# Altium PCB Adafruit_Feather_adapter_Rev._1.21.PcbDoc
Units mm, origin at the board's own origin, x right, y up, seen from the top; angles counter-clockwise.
Board outline 65 x 56 mm, 2 copper layers (Top Layer, Bottom Layer), stack 1.586 mm thick; 51 components, 43 nets, 191 pads, 149 vias.
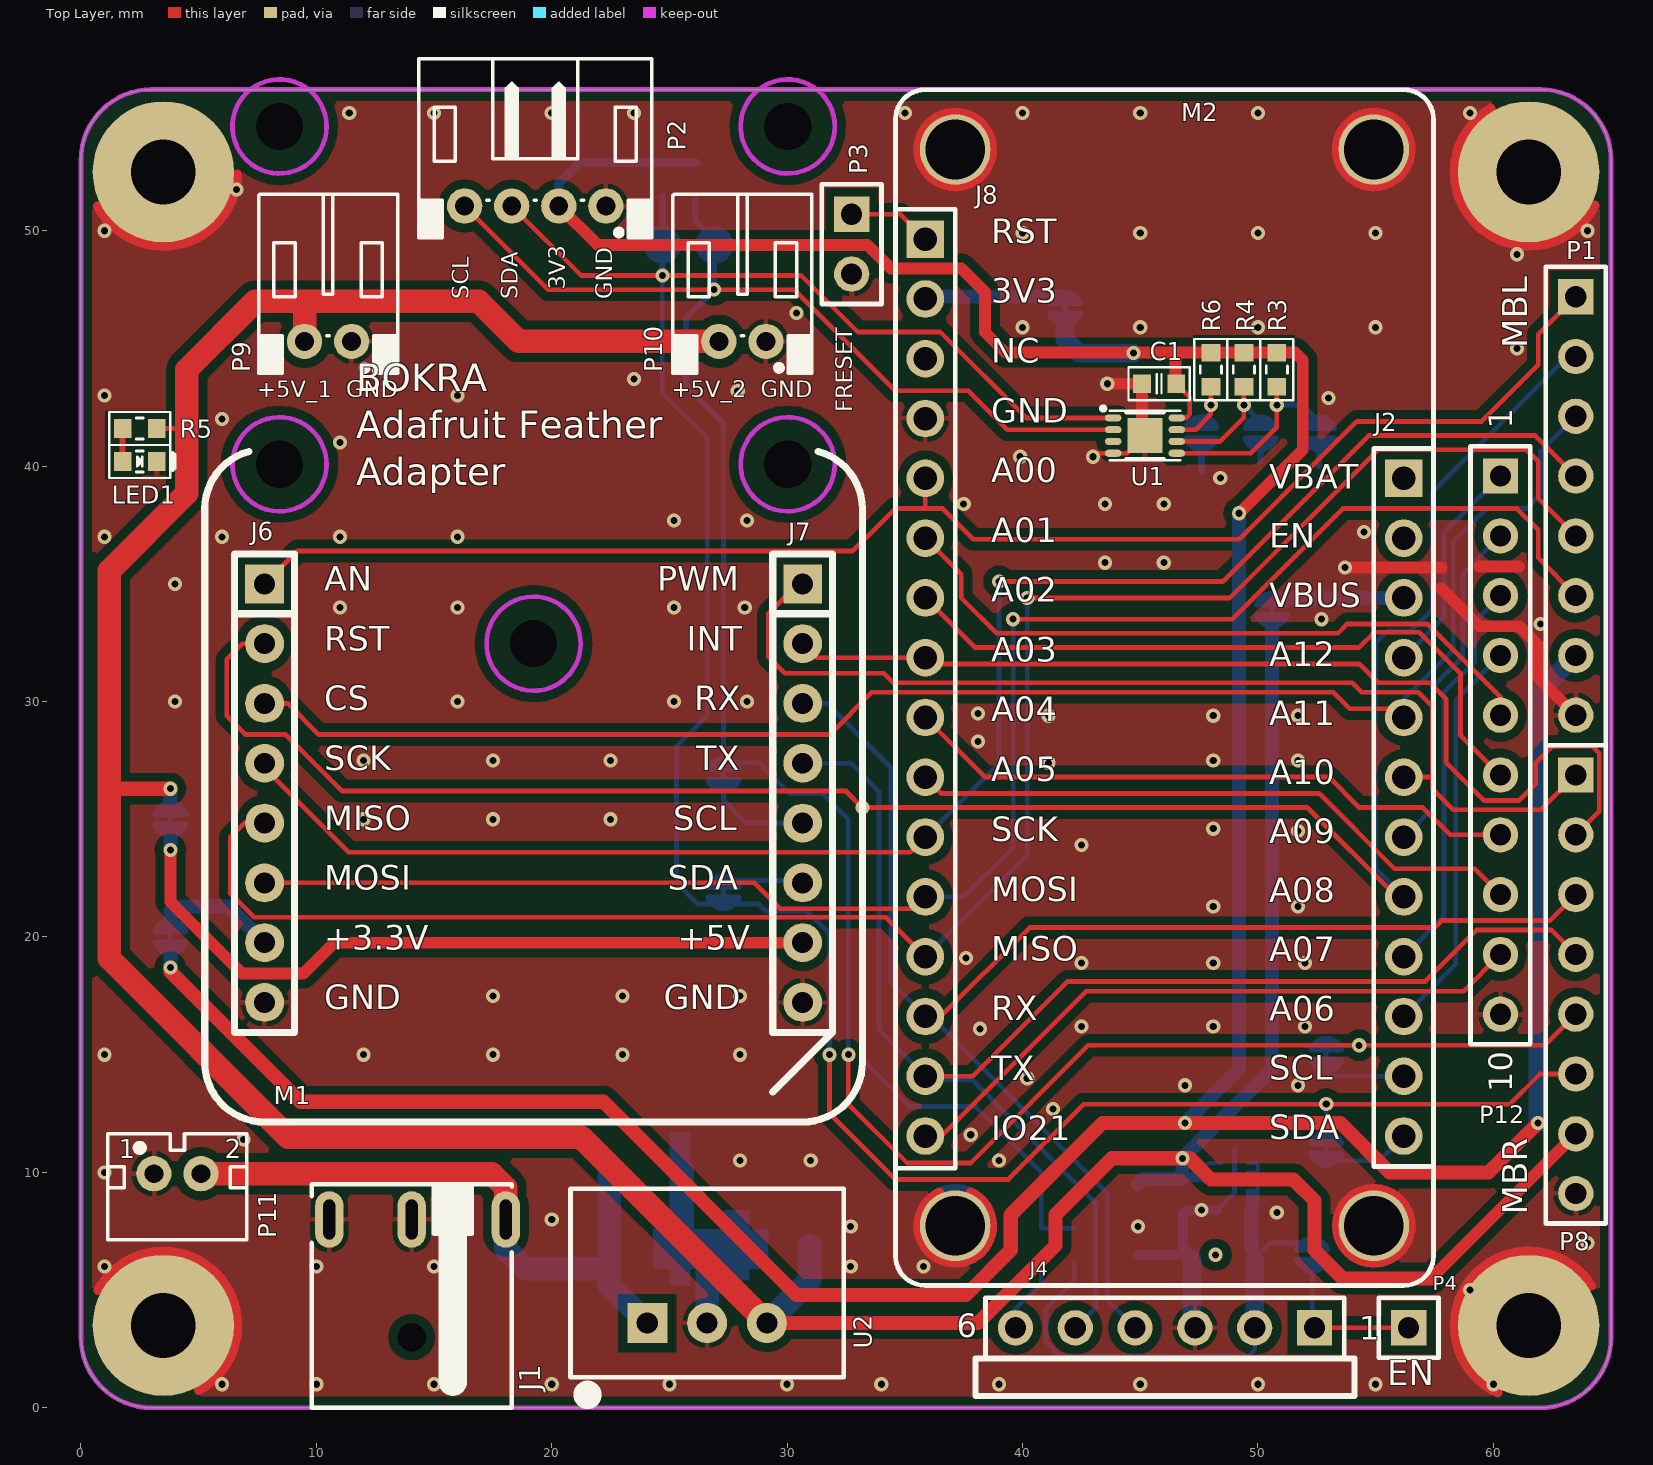
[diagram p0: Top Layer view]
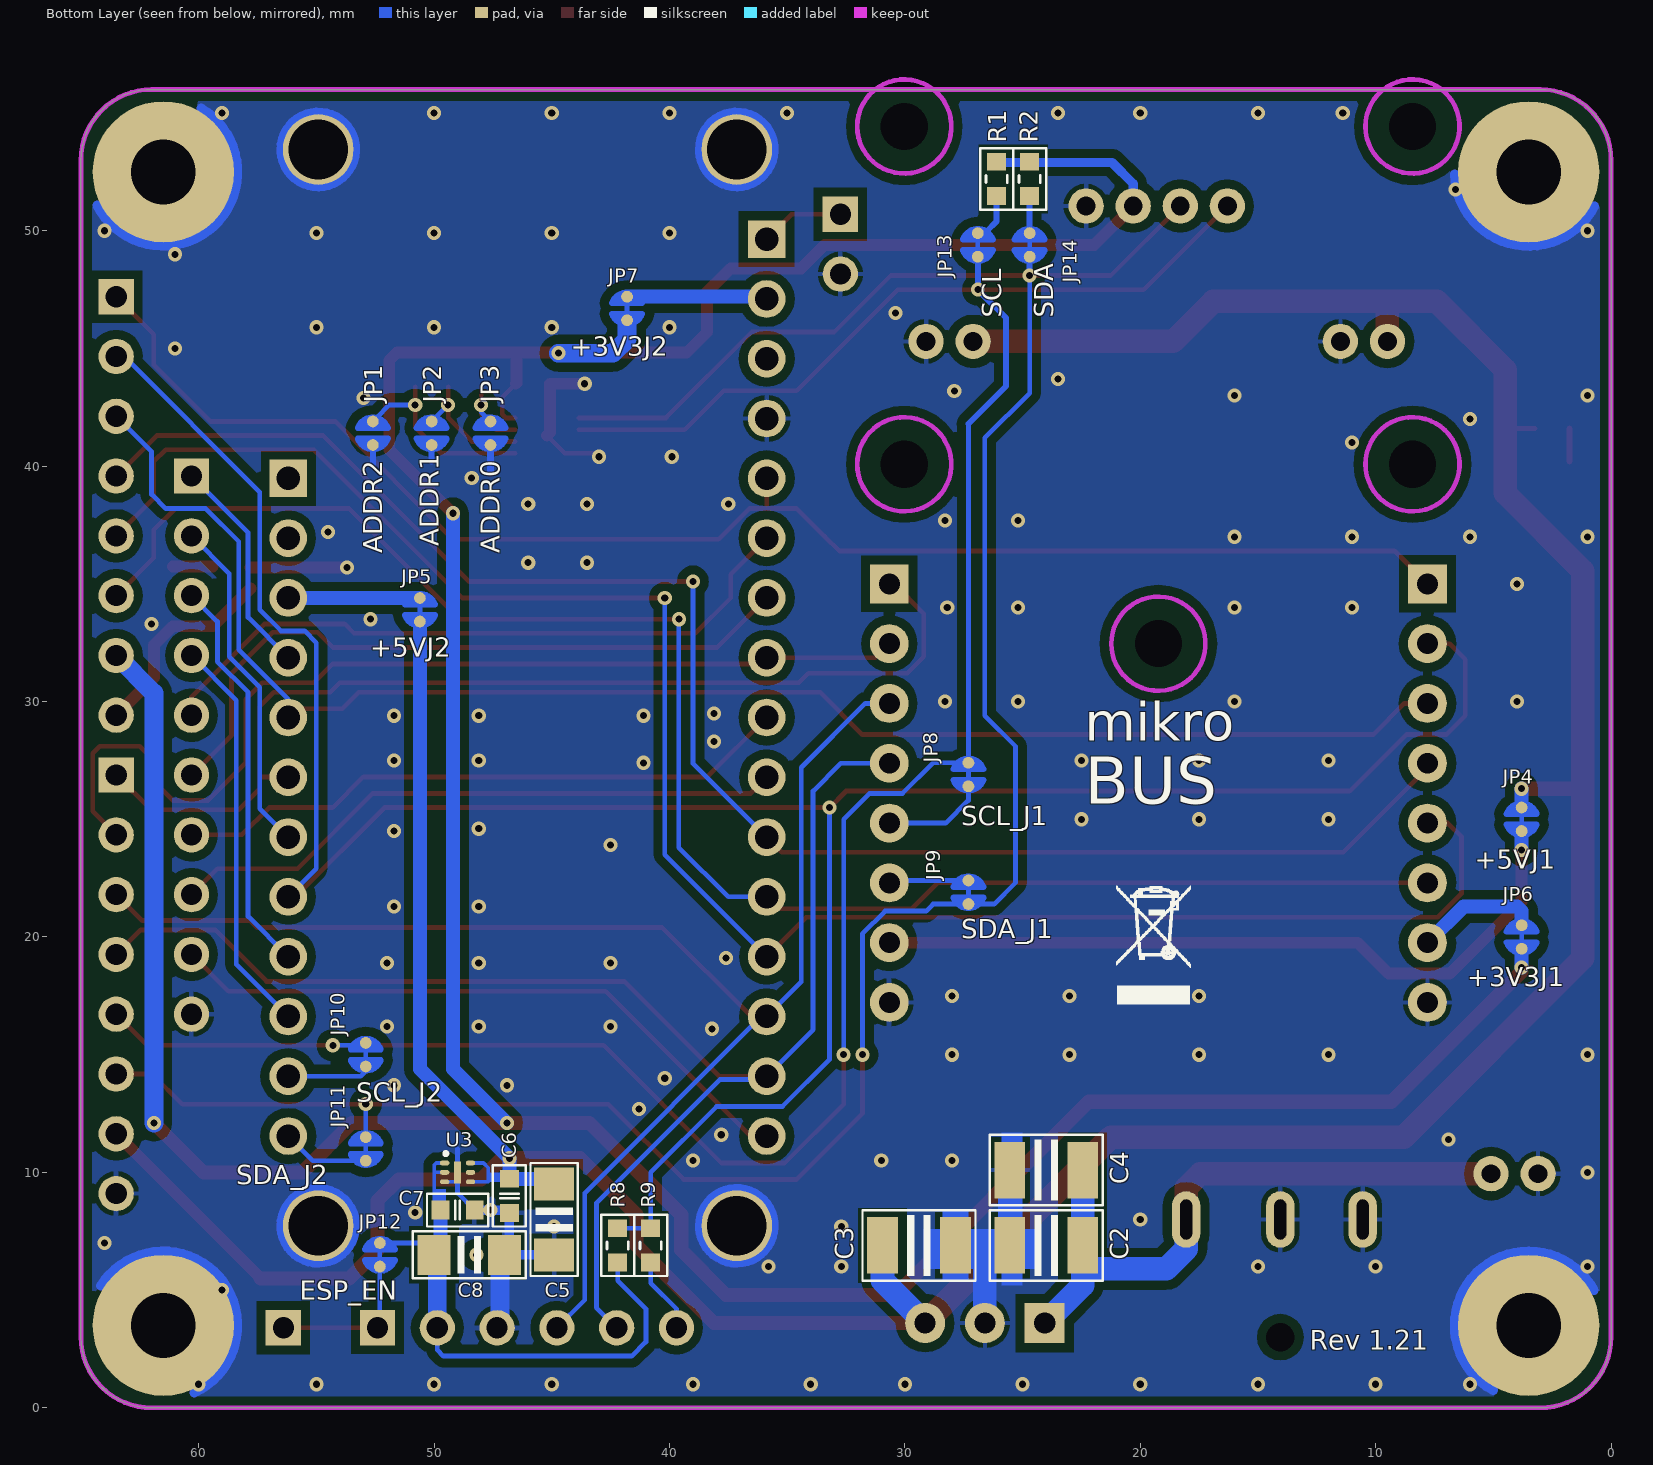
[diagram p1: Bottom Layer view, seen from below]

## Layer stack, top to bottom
Top Solder: solder mask 0.0102, Solder Resist, Dk 3.5
Top Layer: signal copper 0.018
Dielectric1: core 1.55, FR-4, Dk 4.8
Bottom Layer: signal copper 0.018
Bottom Solder: solder mask 0.0102, Solder Resist, Dk 3.5

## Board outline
0,3 0,53 cw(c3,53) 3,56 62,56 cw(c62,53) 65,53 65,3 cw(c62,3) 62,0 3,0 cw(c3,3)

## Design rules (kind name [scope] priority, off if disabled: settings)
BoardOutlineClearance [All] p1: gap=0.25 except(0: Arc-SplitContinuation Track-SplitContinuation SMDPad-SplitContinuation THPad-SplitContinuation Via-SplitContinuation Fill-SplitContinuation Poly-SplitContinuation Region-SplitContinuation Text-SplitContinuation)
Clearance Clearance_Polygon [InPoly] p1: gap=0.381
Clearance [All] p2: gap=0.15
ComponentClearance ComponentClearance_P3-P6 [InComponent('P3') vs InComponent('P6')] p1: gap=0 collisioncheckmode=3 verticalgap=0 showdistances=FALSE
ComponentClearance ComponentClearance_P6-P7 [InComponent('P6') vs InComponent('P7')] p2: gap=0 collisioncheckmode=3 verticalgap=0 showdistances=FALSE
ComponentClearance ComponentClearance_MBL-R [InComponent('P1') vs InComponent('P8')] p3: gap=0 collisioncheckmode=3 verticalgap=0 showdistances=FALSE
ComponentClearance ComponentClearance_M1 [InComponent('M1') vs InComponent('J6') or InComponent('J7')] p4: gap=0 collisioncheckmode=3 verticalgap=0 showdistances=FALSE
ComponentClearance ComponentClearance_M2 [InComponent('M2') vs InComponent('J2') or InComponent('J8') or InComponent('U1') or InComponent('C1') or InComponent('R3') or InComponent('R4') or InComponent('R6')] p5: gap=0 collisioncheckmode=3 verticalgap=0 showdistances=FALSE
ComponentClearance [All] p6: gap=0.25 collisioncheckmode=3 verticalgap=0.25 showdistances=FALSE
DiffPairsRouting [All] p1: maxlimit=0.25 minlimit=0.25 mostfreqgap=0.25 toplayer_minwidth=0.381 toplayer_maxwidth=0.381 toplayer_prefwidth=0.381 bottomlayer_minwidth=0.381 bottomlayer_maxwidth=0.381 bottomlayer_prefwidth=0.381 maxuncoupledlength=12.5
Height [All] p1: minheight=0 maxheight=25 prefheight=12.5
HoleSize HoleSize-PTH [All] p1: absolutevalues=TRUE maxlimit=1270 minlimit=0 maxpercent=80.000 minpercent=20.000
HoleToHoleClearance [All] p1: gap=0.35 allowstackedmicrovias=TRUE
MinimumAnnularRing "Minimum IAR  >0.45mm" [((ObjectKind = 'Pad') OR (ObjectKind = 'Via')) And (Layer = 'MultiLayer') And (HoleDiameter > AsMM(0.45))] p1: minimumring=0.051 // minimum inner annular ring for pads > 0.45mm finished hole size
MinimumAnnularRing "Minimum IAR <=0.45mm" [((ObjectKind = 'Pad') OR (ObjectKind = 'Via')) And (Layer = 'MultiLayer') And (HoleDiameter <= AsMM(0.45))] p2: minimumring=0.051 // minimum inner annular ring for pads <= 0.45mm finished hole size
MinimumSolderMaskSliver [All] p1: minsoldermaskwidth=0
PasteMaskExpansion [All] p1: expansion=-0.025
PlaneClearance PlaneClearance-IPI [All] p1: clearance=0.25
PlaneConnect [All] p1: planeconnectstyle=Relief reliefexpansion=0.175 reliefentries=4 reliefconductorwidth=0.2 reliefairgap=0.2
PolygonConnect PolygonConnect_Via [IsVia] p1: connectstyle=Direct reliefconductorwidth=0.254 reliefentries=4 polygonreliefangle="90 Angle" airgapwidth=0.254
PolygonConnect [All] p2: connectstyle=Relief reliefconductorwidth=0.2 reliefentries=4 polygonreliefangle="90 Angle" airgapwidth=0.2
RoutingCorners [All] p1: cornerstyle=45-Degree minsetback=2.5 maxsetback=2.5
RoutingVias [isvia] p1: holewidth=0.3 width=0.6 viastyle="Through Hole" minholewidth=0.3 minwidth=0.6 maxholewidth=0.5 maxwidth=0.8 // finishet hole size <= 0.45mm
SilkToSilkClearance [All] p1: silktosilkclearance=0
SilkToSolderMaskClearance SilkscreenOverComponentPads [IsPad] p1: minsilkscreentomaskgap=0 clearancetoexposedcopper=TRUE
SolderMaskExpansion [All] p1: expansion=0.1
Width [All] p1: maxlimit=1.5 minlimit=0.15 preferedwidth=0.2 checkconnectedcopper=TRUE
18 further rules are at their usual default settings.

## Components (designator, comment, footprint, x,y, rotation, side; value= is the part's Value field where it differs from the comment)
C1 "100n" C-0603 45.8,43.5 r180 top
C2 "10u/50V" C-1210 24,6.9 r180 bottom
C3 "22u/16V" C-1210 29.4,6.9 r0 bottom
C4 "10u/50V" C-1210 24,10.1 r180 bottom
C5 "10u" C-1206 44.9,8 r90 bottom
C6 "100n" C-0603 46.8,9 r90 bottom
C7 "100n" C-0603 49,8.4 r0 bottom
C8 "10u" C-1206 48.5,6.5 r0 bottom
J1 "54-00125" CONN_54-00125 14.3,5.5 r90 top locked
J2 "CES-112-01-T-S" SCOKET12X01 56.19,39.484 r270 top locked
J4 "Receptacle 2.54mm 1X6" "Receptacle 2.54mm 1X6" 52.4,3.4 r180 top locked
J6 "SSQ-108-01-T-S" MIKROE_ROW_1x8 7.8,35 r0 top
J7 "SSQ-108-01-T-S" MIKROE_ROW_1x8 30.66,35 r0 top
J8 "SLW-116-01-T-S" SCOKET16X01 35.87,49.644 r270 top locked
JP1 "PCB Solder jumper Small" "PCB solder jumper small"#1 52.6,41.4 r270 bottom
JP2 "PCB Solder jumper Small" "PCB solder jumper small"#1 50.1,41.4 r270 bottom
JP3 "PCB Solder jumper Small" "PCB solder jumper small"#2 47.6,41.4 r270 bottom
JP4 "PCB Solder jumper Small connected" "PCB solder jumper small - connected"#1 3.8,25 r270 bottom net-tie
JP5 "PCB Solder jumper Small connected" "PCB solder jumper small - connected"#1 50.6,33.9 r90 bottom net-tie
JP6 "PCB Solder jumper Small connected" "PCB solder jumper small - connected"#1 3.8,20 r90 bottom net-tie
JP7 "PCB Solder jumper Small connected" "PCB solder jumper small - connected"#1 41.8,46.7 r90 bottom net-tie
JP8 "PCB Solder jumper Small connected" "PCB solder jumper small - connected"#2 27.3,26.9 r90 bottom net-tie
JP9 "PCB Solder jumper Small connected" "PCB solder jumper small - connected"#3 27.3,21.9 r270 bottom net-tie
JP10 "PCB Solder jumper Small connected" "PCB solder jumper small - connected"#2 52.9,15 r90 bottom net-tie
JP11 "PCB Solder jumper Small connected" "PCB solder jumper small - connected"#2 52.9,11 r90 bottom net-tie
JP12 "PCB Solder jumper Small connected" "PCB solder jumper small - connected"#4 52.3,6.5 r90 bottom net-tie
JP13 "PCB Solder jumper Small connected" "PCB solder jumper small - connected"#2 26.9,49.4 r90 bottom net-tie
JP14 "PCB Solder jumper Small connected" "PCB solder jumper small - connected"#2 24.7,49.4 r90 bottom net-tie
LED1 "LTST-C193KGKT" LED-0603 2.5,40.2 r180 top
M1 "MIKROBUS HOST" "MIKROBUS HOST CONN." 7.8,35 r0 top locked
M2 "FEATHER" FEATHERHOST 34.6,54.2 r270 top locked
P1 "Header 2.54mm 1x8" CONN_Header_2.54mm_1X8 63.5,47.2 r270 top locked
P2 "S4B-PH-K-S(LF)(SN)" Conn_S4B-PH-K-S 19.3,51.05 r0 top locked
P3 "Header 2.54mm 1X2" CONN_Header_2.54mm_1X2 32.74,50.7 r270 top
P4 "Header 2.54mm 1X1" "Header 2.54mm 1X1" 56.4,3.4 r0 top
P8 "Header 2.54mm 1x8" CONN_Header_2.54mm_1X8 63.5,26.88 r270 top locked
P9 "S2B-PH-K-E" Conn_S2B-PH-K-E 10.5,45.3 r0 top
P10 "S2B-PH-K-E" Conn_S2B-PH-K-E 28.1,45.3 r0 top
P11 "B2B-PH-K-S" "Conn B2B-PH-K-S" 4.1,9.944 r180 top
P12 "Header 2.54mm 1x10" CONN_Header_2.54mm_1X10 60.3,39.58 r270 top locked
R1 "4k7" R-0603 26.1,52.2 r90 bottom
R2 "4k7" R-0603 24.7,52.2 r90 bottom
R3 "10k" R-0603 50.8,44.1 r90 top
R4 "10k" R-0603 49.4,44.1 r90 top
R5 "1k" R-0603 2.5,41.6 r0 top
R6 "10k" R-0603 48,44.1 r90 top
R8 "10k" R-0603 42.2,6.9 r270 bottom
R9 "0R0" R-0603 40.8,6.9 r270 bottom
U1 "LM75BTP,147" DFN50P200X300X75-8T150 45.2,41.3 r0 top
U2 "P78E05-1000" SIP-3 26.6,3.6 r0 top
U3 "MIC5528-3.3YMX-TR" DFN40P120X120X40-6T30X94 49,10 r180 bottom

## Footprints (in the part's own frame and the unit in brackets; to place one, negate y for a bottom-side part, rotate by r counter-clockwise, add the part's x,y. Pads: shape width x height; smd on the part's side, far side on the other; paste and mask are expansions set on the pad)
C-0603 [mm] "Chip Capacitor; Body 1.6 x 0.8 mm (LxW typ)"
  rect 0.75x0.8 smd paste-0.025: 1(-0.725,0) 2(0.725,0)
  silkscreen extent -1.3,-0.7 1.3,0.7, body extent -0.8,-0.48 0.8,0.44, height 0.8
C-1206 [mm] "Chip Capacitor; Body 3.2 x 1.6 mm (LxW typ)"
  rect 1.4x1.7 smd paste-0.025 mask+0.08: 1(-1.5,0) 2(1.5,0)
  silkscreen extent -2.4,-1 2.4,1, body extent -1.65,-0.8 1.55,0.8, height 1.05
C-1210 [mm] "Chip Capacitor; Body 3.2 x 2.5 mm (LxW typ)"
  rect 1.3x2.4 smd: 1(-1.55,0) 2(1.55,0)
  silkscreen extent -2.4,-1.5 2.4,1.5, body extent -1.65,-1.25 1.55,1.25, height 1.2
"Conn B2B-PH-K-S" [mm] "2 mm pitch/Disconnectable Crimp style connector"
  round 1.5 hole 0.8: 1(1,0) 2(-1,0)
  silkscreen extent -2.95,-1.7 2.95,2.8, body extent -2.95,-1.7 2.95,2.8, height 6.01
CONN_54-00125 [mm] "Power Barrel Conn Jack 1.1/3.5 mm (ID/OD), TH, RA"
  oval 2.4x1.2 hole 0.5 slot 1.7 at 0 deg paste-0.025 mask+0.1: 1(2.5,-3.75) 2(2.5,3.75) 3(2.5,0.25)
  round 1.15 hole 1.2 unplated paste-5 mask+0.1: M(-2.5,0.25)
  silkscreen extent -5.5,-4 4,4.5, body extent -5.5,-4 4,4.5, height 5.51
CONN_Header_2.54mm_1X2 [mm] "2.54mm pitch single row wire to board connector"
  rect 1.5x1.5 hole 0.9: 1(0,0)
  round 1.5 hole 0.9: 2(2.54,0)
  silkscreen extent -1.27,-1.27 3.81,1.27, body extent -1.26,-1.29 3.82,1.25, height 8.54
CONN_Header_2.54mm_1X8 [mm] "2.54mm pitch single row wire to board connector"
  rect 1.5x1.5 hole 0.9: 1(0,0)
  round 1.5 hole 0.9: 2(2.54,0)
  round 1.5 hole 0.9 mask+0.05: 3(5.08,0) 4(7.62,0) 5(10.16,0) 6(12.7,0) 7(15.24,0) 8(17.78,0)
  silkscreen extent -1.27,-1.27 19.05,1.27, body extent -1.26,-1.29 19.06,1.25, height 8.54
CONN_Header_2.54mm_1X10 [mm] "2.54mm pitch single row wire to board connector"
  rect 1.5x1.5 hole 0.9: 1(0,0)
  round 1.5 hole 0.9: 2(2.54,0)
  round 1.5 hole 0.9 mask+0.05: 3(5.08,0) 4(7.62,0) 5(10.16,0) 6(12.7,0) 7(15.24,0) 8(17.78,0) 9(20.32,0) 10(22.86,0)
  silkscreen extent -1.27,-1.27 24.13,1.27, body extent -1.27,-1.27 24.13,1.27, height 8.54
Conn_S2B-PH-K-E [mm] "2.00 mm pitch wire to board connector, THT"
  round 1.5 hole 0.8: 1(1,0) 2(-1,0)
  silkscreen extent -2.95,-1.35 2.95,6.25, body extent -2.95,-1.3 2.95,6.3, height 4.82
Conn_S4B-PH-K-S [mm] "2.00 mm pitch wire to board connector, THT"
  round 1.5 hole 0.8: 1(3,0) 2(1,0) 3(-1,0) 4(-3,0)
  silkscreen extent -4.95,-1.35 4.95,6.25, body extent -4.95,-1.3 4.95,6.3, height 4.81
DFN40P120X120X40-6T30X94 [mm] "DFN, 6-Leads, Body 1.2x1.2mm, Pitch 0.4mm"
  oval 0.4x0.2 smd paste-0.025 mask+0.05: 1(-0.55,0.4) 2(-0.55,0) 3(-0.55,-0.4) 4(0.55,-0.4) 5(0.55,0) 6(0.55,0.4)
  rect 0.3x0.94 smd paste-5 mask+0.1: 7(0,0)
  silkscreen extent -0.55,0.75 -0.45,0.85, body extent -0.6,-0.6 0.6,0.6, height 0.41
DFN50P200X300X75-8T150 [mm] "DFN, 8-Leads, Body 3x2mm, Pitch 0.5mm"
  oval 0.7x0.3 smd paste-0.025 mask+0.1: 1(-1.35,0.75) 2(-1.35,0.25) 3(-1.35,-0.25) 4(-1.35,-0.75) 5(1.35,-0.75) 6(1.35,-0.25) 7(1.35,0.25) 8(1.35,0.75)
  rect 1.5x1.5 smd paste-5 mask+0.1: 9(0,0)
  silkscreen extent -1.85,-1.05 1.5,1.22, body extent -1.5,-1 1.5,1, height 0.8
FEATHERHOST [mm]
  round 3 hole 2.54: ""(0.746,20.32) ""(0.746,2.54) ""(46.466,20.32) ""(46.466,2.54)
  round 1 on Mech1: ""(42.656,21.59) ""(42.656,1.27)
  silkscreen extent -1.79,0 49.01,22.86
"Header 2.54mm 1X1" [mm] "2.54mm pitch single row wire to board connector"
  rect 1.5x1.5 hole 0.9: 1(0,0)
  silkscreen extent -1.27,-1.27 1.28,1.27
LED-0603 [mm] "Body 1.6 x 0.8 mm (LxW typ)"
  rect 0.75x0.8 smd paste-0.025: 1(0.725,0) 2(-0.725,0)
  silkscreen extent -1.51,-0.7 1.3,0.7, body extent -0.81,-0.4 0.81,0.4, height 0.6
"MIKROBUS HOST CONN." [mm]
  round 1 on Mech1: ""(0,0) ""(22.86,0)
  silkscreen extent -2.54,-22.86 25.4,5.63
MIKROE_ROW_1x8 [mil]
  rect 65x65 hole 35: 1(0,0)
  round 65 hole 35: 2(0,-100) 3(0,-200) 4(0,-300) 5(0,-400) 6(0,-500) 7(0,-600) 8(0,-700)
  silkscreen extent -50,-750 50,50, body extent -49,-755 49,55, height 335
"PCB solder jumper small"#1 [mm] "PCB solder jumper small"
  round 0.5 smd paste-5 mask-5: 1(-0.5,0) 2(0.5,0)
  Top Layer lines w0.25: 0.225,0.638 0.225,-0.638 ; -0.225,0.638 -0.225,-0.638 ; 0.235,0.634 cw(c0.005,0) 0.68,0 cw(c0.005,0) 0.235,-0.634 ; -0.235,0.634 ccw(c-0.005,0) -0.66,0.16 ccw(c-0.005,0) -0.235,-0.634 ; 0.45,0.5 0.45,0 0.45,-0.5 ; -0.45,0.5 -0.45,0 -0.45,-0.5
"PCB solder jumper small"#2 [mm] "PCB solder jumper small"
  round 0.5 smd paste-5 mask-5: 1(-0.5,0) 2(0.5,0)
  Top Layer lines w0.25: 0.225,0.638 0.225,0 0.225,-0.638 ; -0.225,0.638 -0.225,-0.638 ; 0.235,0.634 cw(c0.005,0) 0.68,0 cw(c0.005,0) 0.235,-0.634 ; -0.235,0.634 ccw(c-0.005,0) -0.66,-0.16 ccw(c-0.005,0) -0.235,-0.634 ; 0.45,0.5 0.45,0 0.45,-0.5 ; -0.45,0.5 -0.45,0 -0.45,-0.5
"PCB solder jumper small - connected"#1 [mm] "PCB solder jumper small - connected"
  round 0.5 smd paste-5 mask-5: 1(-0.5,0) 2(0.5,0)
  Top Layer lines w0.2: 0.5,0 0.45,0 0.225,0 -0.225,0 -0.45,0 -0.5,0
  Top Layer lines w0.25: 0.225,0.638 0.225,0 0.225,-0.638 ; -0.225,0.638 -0.225,0 -0.225,-0.638 ; 0.235,0.634 cw(c0.005,0) 0.235,-0.634 ; -0.235,0.634 ccw(c-0.005,0) -0.68,0 ccw(c-0.005,0) -0.235,-0.634 ; 0.45,0.5 0.45,0 0.45,-0.5 ; -0.45,0.5 -0.45,0 -0.45,-0.5
"PCB solder jumper small - connected"#2 [mm] "PCB solder jumper small - connected"
  round 0.5 smd paste-5 mask-5: 1(-0.5,0) 2(0.5,0)
  Top Layer lines w0.2: -0.5,0 0.5,0
  Top Layer lines w0.25: -0.225,-0.638 -0.225,0.638 ; 0.225,-0.638 0.225,0.638 ; -0.235,-0.634 cw(c-0.005,0) -0.235,0.634 ; 0.235,-0.634 ccw(c0.005,0) 0.235,0.634 ; -0.45,-0.5 -0.45,0.5 ; 0.45,-0.5 0.45,0.5
"PCB solder jumper small - connected"#3 [mm] "PCB solder jumper small - connected"
  round 0.5 smd paste-5 mask-5: 1(-0.5,0) 2(0.5,0)
  Top Layer lines w0.2: 0.5,0 0.45,0 0.225,0 -0.225,0 -0.45,0 -0.5,0
  Top Layer lines w0.25: 0.225,0.638 0.225,-0.638 ; -0.225,0.638 -0.225,-0.638 ; 0.235,0.634 cw(c0.005,0) 0.235,-0.634 ; -0.235,0.634 ccw(c-0.005,0) -0.5,-0.458 ccw(c-0.005,0) -0.235,-0.634 ; 0.45,0.5 0.45,-0.5 ; -0.45,0.5 -0.45,0 -0.45,-0.5
"PCB solder jumper small - connected"#4 [mm] "PCB solder jumper small - connected"
  round 0.5 smd paste-5 mask-5: 1(-0.5,0) 2(0.5,0)
  Top Layer lines w0.2: -0.5,0 -0.45,0 -0.225,0 0.225,0 0.45,0 0.5,0
  Top Layer lines w0.25: -0.225,-0.638 -0.225,0.638 ; 0.225,-0.638 0.225,0.638 ; -0.235,-0.634 cw(c-0.005,0) -0.235,0.634 ; 0.235,-0.634 ccw(c0.005,0) 0.5,-0.458 ccw(c0.005,0) 0.235,0.634 ; -0.45,-0.5 -0.45,0.5 ; 0.45,-0.5 0.45,0 0.45,0.5
R-0603 [mm] "Chip Resistor; Body 1.6 x 0.9 mm (LxW typ)"
  rect 0.75x0.8 smd paste-0.025: 1(-0.725,0) 2(0.725,0)
  silkscreen extent -1.3,-0.7 1.3,0.7, body extent -0.8,-0.4 0.8,0.4, height 0.38
"Receptacle 2.54mm 1X6" [mm] "2.54mm pitch single row wire to board connector"
  rect 1.5x1.5 hole 0.9: 1(0,0)
  round 1.5 hole 0.9: 2(2.54,0)
  round 1.5 hole 0.9 mask+0.05: 3(5.08,0) 4(7.62,0) 5(10.16,0) 6(12.7,0)
  silkscreen extent -1.27,-1.27 13.97,1.27, body extent -1.27,-1.27 13.97,1.27, height 8.5
SCOKET12X01 [mm]
  rect 1.6x1.6 hole 1: 1(0,0)
  round 1.6 hole 1: 2(2.54,0) 3(5.08,0) 4(7.62,0) 5(10.16,0) 6(12.7,0) 7(15.24,0) 8(17.78,0) 9(20.32,0) 10(22.86,0) 11(25.4,0) 12(27.94,0)
  silkscreen extent -1.27,-1.27 29.24,1.27, body extent -1.24,-1.27 29.24,1.27, height 7
SCOKET16X01 [mm]
  rect 1.6x1.6 hole 1: 1(0,0)
  round 1.6 hole 1: 2(2.54,0) 3(5.08,0) 4(7.62,0) 5(10.16,0) 6(12.7,0) 7(15.24,0) 8(17.78,0) 9(20.32,0) 10(22.86,0) 11(25.4,0) 12(27.94,0) 13(30.48,0) 14(33.02,0) 15(35.56,0) 16(38.1,0)
  silkscreen extent -1.27,-1.27 39.47,1.27, body extent -1.24,-1.22 39.4,1.32, height 7
SIP-3 [mm] "SIP3 PE7805"
  rect 1.7x1.7 hole 0.9: 1(-2.54,0)
  round 1.7 hole 0.9: 2(0,0) 3(2.54,0)
  silkscreen extent -5.8,-3.15 5.8,5.7, body extent -5.8,-2.3 5.8,5.7, height 10.41

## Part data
C1 C6 C7: library part C0603-100n-50V-X7R, "Capacitor ceramic 100n X7R 50V 0603"
C2 C4: library part C1210-10u-50V-X7R, "Capacitor ceramic 10u ±10% X7R 50V 1210"
C3: library part C1210-22u-16V-X7R, "Capacitor ceramic 22u ±15% X7R 16V 1210"
C5 C8: library part C1206-10u-16V-X7R, "Capacitor ceramic 10u ±10 X7R 16V 1206"
J1: library part "Conn Barrel 54-00125", "Barrel Power Connector, 1.1/3.5mm (ID/OD), 48V/3.5A"
J2: library part ROW_01X12
J4: library part "Conn Receptacle 2.54mm 1X6", "2.54mm pitch 6 pin (1x6) top entry wire to board connector THT"
J6 J7: library part MIKROE_ROW_01X08
J8: library part ROW_01X16
JP4 JP5 JP6 JP7 JP8 JP9 JP10 JP11 JP12 JP13 JP14: "PCB Solder jumper Small - connected"
LED1: "Standard LEDs - SMD Green, 571nm 12mcd, 5mA"
M1: "mikroBUS Host Socket"
P1 P8: library part "Conn Header 2.54mm 1X8", "2.54mm pitch 8 pin (1x8) top entry wire to board connector THT"
P2: library part "Conn S4B-PH-K-S(LF)(SN)", "2mm pitch 4 pin side entry wire to board connector THT"
P3: library part "Conn Header 2.54mm 1X2", "2.54mm pitch 2 pin (1x2) top entry wire to board connector THT"
P4: library part "Conn Header 2.54mm 1X1", "2.54mm pitch 1 pin (1x1) top entry wire to board connector THT"
P9 P10: library part "Conn S2B-PH-K-E", "2.00mm pitch 2 pin side entry wire to board connector, THT"
P11: library part "Conn B2B-PH-K-S", "2.00mm pitch 2 pin top entry wire to board connector, THT"
P12: library part "Conn Header 2.54mm 1X10", "2.54mm pitch 10 pin (1x10) top entry wire to board connector THT"
R1 R2: library part R0603-4k7-1, "Resistor 4k7 ±1% 0603"
R3 R4 R6 R8: library part R0603-10k-1, "Resistor 10k ±1% 0603"
R5: library part R0603-1k-1, "Resistor 1k ±1% 0603"
R9: library part R0603-0R0, "Resistor 0R0 0603"
U1: "SENSOR DIGITAL -55C-125C 8HWSON"
U2: "DC-DC NON-ISOLATED, 1.0 A, 8-36 V IN"
U3: "IC REG LINEAR 3.3V 500MA 6TDFN"

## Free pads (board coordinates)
  round 6 hole 2.75 paste-5 mask+0: 0(3.5,3.5) 0(3.5,52.5) 0(61.5,3.5) 0(61.5,52.5)
  round 0 hole 2 unplated: 1(8.435,40.08) 1(8.435,54.43) 1(19.23,32.46) 1(30.025,40.08) 1(30.025,54.43)

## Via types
v1: diameter 0.6, hole 0.3, Top Layer to Bottom Layer, tented both sides, 149 vias

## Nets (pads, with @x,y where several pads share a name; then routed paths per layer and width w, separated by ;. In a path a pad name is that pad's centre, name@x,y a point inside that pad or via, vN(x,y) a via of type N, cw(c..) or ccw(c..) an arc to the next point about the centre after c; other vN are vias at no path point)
+3V3: C1.1 JP6.1 JP7.1 P1.7 P2.2 R1.2 R2.2 R3.2 R4.2 R6.2 U1.8 | length 175.3
  Top Layer w0.2: C1.1 47.1,42.925 47.1,42.2 46.95,42.05 U1.8
  Top Layer w0.5: P2.2 21.95,49.4 33.4,49.4 34.4,48.4 37.4,48.4 38.4,47.4 38.4,45.7 39.275,44.825 46.5,44.825 ; C1.1 46.5,43.525 46.5,44.825 ; v1(49.2,38) 51.9,40.7 51.9,44.5 51.575,44.825 R3.2 R4.2 R6.2 46.5,44.825
  Top Layer w0.6: v1(3.8,18.7) 3.8,18.524 9.324,13 22.2,13 30.4,4.8 37.6,4.8 39.5,6.7 39.5,8.2 43.4,12.1 53.5,12.1 55.6,10 59.8,10 v1(61.9,12.1)
  Bottom Layer w0.4: P2.2 20.3,52 21.2,52.9 R1.2@26.1,52.9
  Bottom Layer w0.6: v1(3.8,18.7) 3.8,19.32 JP6.1 ; v1(46.9,12.1) 49.2,14.4 v1(49.2,38)
  Bottom Layer w0.8: JP7.1 41.8,46.02 41.8,45.4 42.4,44.8 v1(44.72,44.8) ; v1(61.9,12.1) 61.9,30.36 P1.7
+3V3_ESP: C7.2 C8.2 J4.2 JP12.2 R8.2 U3.1 U3.2 | length 24
  Bottom Layer w0.15: U3.2 50,10 ; U3.1 49.9,10.4 50,10.3 50,10 ; C7.2@49.9,8.5 50,8.6 50,10
  Bottom Layer w0.2: R8.2 42.2,5.4 41,4.2 41,2.8 41.6,2.2 49.6,2.2 49.86,2.46 J4.2 ; 49.725,7.9 49.825,7.8 ; C8.2 50.5,7 51.842,7 JP12.2
  Bottom Layer w0.6: C8.2@49.7,6.8 49.725,6.825 49.725,7.9 C7.2 ; C8.2@49.8,6.3 C8.2@49.86,6.24
  Bottom Layer w0.8: J4.2 C8.2@49.86,6.24
+3V3J1: J6.7 JP6.2 | length 5.3
  Bottom Layer w0.6: JP6.2 3.8,21.1 4,21.3 6.26,21.3 J6.7
+3V3J2: J8.2 JP7.2 | length 6
  Bottom Layer w0.6: J8.2 35.966,47.2 JP7.2
+5V: C3.2 C5.2 C6.2 JP4.1 JP5.1 P8.7 P9.2 P10.2 R5.2 U2.3 U3.4 U3.6 | length 169.1
  Top Layer w0.2: R5.2 4.4,41.6 4.5,41.5
  Top Layer w0.5: 57.36,5.5 P8.7
  Top Layer w0.6: 1.2,26.4 1.3,26.3 v1(3.8,26.3) ; U2.3 38.1,3.6 41.4,6.9 41.4,8.2 43.8,10.6 v1(46.8,10.6) 47.1,10.6 48,9.7 51.5,9.7 52.4,8.8 52.4,6.7 53.6,5.5 57.36,5.5
  Top Layer w1: P9.2 9.5,46.9 9.6,47 ; P10.2@26.95,45.45 P10.2 18.6,45.3 18.45,45.45 16.9,47 9.6,47 ; U2.3 21.24,11.5 8.8,11.5 1.2,19.1 1.2,26.4 1.2,35.55 4.5,38.85 4.5,41.5 4.5,44.1 7.4,47 9.6,47
  Bottom Layer w0.15: U3.4 47.7,9.6 47.7,10.2 47.9,10.4 U3.6
  Bottom Layer w0.6: JP4.1@3.8,25.68 v1(3.8,26.3) ; C5.2 45.125,9.725 C6.2 v1(46.8,10.6) 50.6,14.4 50.6,33.22 JP5.1
  Bottom Layer w1: U2.3 30.95,5.41 C3.2
+5VJ1: J7.7 JP4.2 | length 31.5
  Top Layer w0.5: v1(3.8,23.7) 3.8,21.5 6.855,18.445 9.445,18.445 10.76,19.76 J7.7
  Bottom Layer w0.6: v1(3.8,23.7) JP4.2@3.8,24.32
+5VJ2: J2.3 JP5.2 | length 5.6
  Bottom Layer w0.6: JP5.2 56.186,34.4 J2.3
+VCC: C2.2 C4.2 J1.1 P11.2 U2.1 | length 27.4
  Top Layer w1: P11.2 17.456,9.944 18.05,9.35 J1.1
  Bottom Layer w1: J1.1 18.05,6.75 18.9,5.9 C2.2@22.1,5.9 ; C4.2 C2.2 22.45,5.21 U2.1
A1: J8.6 P12.5 | length 28.9
  Top Layer w0.2: J8.6 37.4,35.414 37.4,34.4 38.9,32.9 53.4,32.9 53.8,33.3 57.2,33.3 60.3,30.2 P12.5
A2: J8.7 P12.6 | length 29.6
  Top Layer w0.2: J8.7 37.974,32.3 54.3,32.3 54.95,32.95 56.85,32.95 58.6,31.2 58.6,28.58 P12.6
A4: J8.9 P12.7 | length 26.5
  Top Layer w0.2: J8.9 38.394,26.8 53,26.8 54.3,25.5 57,25.5 58.16,24.34 P12.7
A5: J8.10 P12.8 | length 26.5
  Top Layer w0.2: J8.10 36.554,26.1 52.6,26.1 55.8,22.9 59.2,22.9 P12.8
ADDR0: JP3.1 R6.1 U1.7 | length 3.8
  Top Layer w0.2: U1.7 47.35,41.55 48,42.2 v1(48,42.6) R6.1
  Bottom Layer w0.2: JP3.1 47.76,42.06 48,42.3 v1(48,42.6)
ADDR1: JP2.1 R4.1 U1.6 | length 5.6
  Top Layer w0.2: U1.6 48.4,41.05 49.4,42.05 v1(49.4,42.6) R4.1
  Bottom Layer w0.2: v1(49.4,42.6) 49.94,42.06 JP2.1
ADDR2: JP1.1 R3.1 U1.5 | length 8.5
  Top Layer w0.2: U1.5 49.7,40.55 50.8,41.65 v1(50.8,42.6) R3.1
  Bottom Layer w0.2: v1(50.8,42.6) 51.9,42.6 52.44,42.06 JP1.1
AN: J6.1 J8.5 P1.1 | length 64.1
  Top Layer w0.2: 33.393,37.007 34.586,38.2 35.8,38.2 ; J8.5 35.87,38.27 35.8,38.2 ; P1.1 61.9,45.6 61.9,44.3 59.5,41.9 54.2,41.9 49.2,36.9 37.9,36.9 36.6,38.2 35.8,38.2
  Top Layer w0.203: J6.1@7.6,35 J6.1 9.2,36.4 32.786,36.4 33.393,37.007
CS: J2.5 J6.3 P1.3 | length 67.1
  Top Layer w0.203: J6.3@7.6,29.92 8.78,29.92 10.1,28.6 31.8,28.6 33.6,30.4 53.2,30.4 53.9,29.7 55.814,29.7 J2.5
  Bottom Layer w0.2: J2.5 56.19,30.09 58.3,32.2 58.3,36.8 59.7,38.2 61.4,38.2 62,38.8 62,40.62 P1.3
FRESET: J8.1 P3.1 | length 3.6
  Top Layer w0.203: P3.1 34.814,50.7 J8.1
GND: C1.2 C2.1 C3.1 C4.1 C5.1 C6.1 C7.1 C8.1 J1.2 J1.3 J4.3 J6.8 J7.8 J8.4 JP1.2 JP2.2 JP3.2 LED1.2 M2.@37.14,7.734 M2.@37.14,53.454 M2.@54.92,7.734 M2.@54.92,53.454 P1.8 P2.1 P3.2 P8.8 P9.1 P10.1 P11.1 P12.10 pad.0 U1.4 U1.9 U2.2 U3.3 U3.7 | length 208.7
  Top Layer w0.2: v1(43,40.4) 43.15,40.55 U1.4 44.45,40.55 U1.9
  Top Layer w0.4: 0.704,51.05 ccw(c3.5,52.5) 6.648,52.402 ; 0.727,4.995 cw(c3.5,3.5) 5.014,0.738 ; 36.473,9.163 ccw(c37.14,7.734) 37.806,9.163 ; 38.713,53.361 cw(c37.14,53.454) 38.716,53.454 ; 56.493,53.361 cw(c54.92,53.454) 56.496,53.454 ; 59.883,55.203 ccw(c61.5,52.5) 64.311,51.078 ; 60.179,0.641 cw(c61.5,3.5) 64.16,5.188 ; 56.496,7.734 ccw(c54.92,7.734) 56.496,7.734
  Top Layer w0.5: v1(43.6,43.5) C1.2 45.075,41.425 U1.9 ; v1(53.7,35.7) 57.8,35.7 ; 57.8,34.8 59.4,33.2 61.1,33.2 61.9,32.4 61.9,31.02 P1.8 ; 59.4,35.74 61.1,35.74
  Bottom Layer w0.15: U3.7@49,9.6 U3.3
  Bottom Layer w0.2: C7.1 49,9.125 49,9.15 ; 49,9.4 49,9.15 ; 49,11 U3.7 49,9.6 49,9.15
  Bottom Layer w0.25: 50.1,40.2 50.1,40.72 JP2.2 ; 52.6,40 52.6,40.72 JP1.2
  Bottom Layer w0.3: 47.6,39.8 47.6,40.72 JP3.2
  Bottom Layer w0.4: 0.704,51.05 ccw(c3.5,52.5) 6.648,52.402 ; 0.727,4.995 cw(c3.5,3.5) 5.014,0.738 ; 38.713,7.641 cw(c37.14,7.734) 38.716,7.734 ; 38.713,53.361 cw(c37.14,53.454) 38.716,53.454 ; C5.1 46.8,6.5 C8.1@47,6.7 ; C8.1@46.8,6.8 C6.1 ; C6.1@46.9,8.3 47,8.4 v1(47.6,8.4) C7.1 ; 56.493,7.641 cw(c54.92,7.734) 56.496,7.734 ; 56.493,53.361 cw(c54.92,53.454) 56.496,53.454 ; 59.883,55.203 ccw(c61.5,52.5) 64.311,51.078 ; 60.179,0.641 cw(c61.5,3.5) 64.16,5.188
  Bottom Layer w0.6: C8.1 C8.1@47.2,6.3
  Bottom Layer w0.8: C8.1@47.2,6.3 47.2,3.52 J4.3
  Bottom Layer w1: C2.1 C2.1@25.6,6.9 ; C4.1 25.55,6.95 C2.1@25.6,6.9 ; C2.1@25.7,6.8 C2.1@25.6,6.9 ; 26.5,7 26.6,6.9 ; U2.2 26.6,6.9 ; C3.1@27.8,7.1 27.6,6.9 26.6,6.9 ; C2.1@25.6,6.9 26.6,6.9
  other v1: 6,1 10,1 15,1 20,1 25,1 30,1 34,1 39,1 45,1 50,1 55,1 60,1 59,5 1,6 10,6 15,6 32.7,6 35.8,6 64,7 32.7,7.7 44.9,7.7 20,8 50.8,8.3 1,10 28,10.5 31,10.5 39,10.5 6.9,11.4 37.8,11.6 41.3,12.7 46.9,13.7 51.7,13.7 40.2,14 1,15 12,15 17.5,15 23,15 28,15 38.2,16.1 42.5,16.2 48.1,16.2 52,16.2 17.5,17.5 23,17.5 28,17.5 42.5,18.9 48.1,18.9 52,18.9 37.6,19.1 48.1,21.3 51.7,21.3 42.5,23.9 51.7,24.5 48.1,24.6 12,25 17.5,25 22.5,25 41.1,27.4 12,27.5 17.5,27.5 22.5,27.5 48.1,27.5 51.7,27.5 38.1,28.3 41.1,29.4 48.1,29.4 51.7,29.4 38.1,29.5 4,30 16,30 25.2,30 28.3,30 62,33.3 52.7,33.5 11,34 16,34 25.2,34 28.2,34 4,35 43.5,35.9 46,35.9 1,37 6,37 11,37 16,37 54.5,37.2 25.2,37.7 28.3,37.7 37.5,38.4 43.5,38.4 46,38.4 48.4,39.5 39.9,40.4 11,41 6,42 53,42.9 1,43 16,43 27.9,43.2 23.5,43.7 61,45 40,45.9 45,45.9 50,45.9 55,45.9 30.4,46.5 61,49 40,49.9 45,49.9 50,49.9 55,49.9 1,50 64,50 6.611,51.75 11.4,55 15,55 20,55 23.5,55 35,55 40,55 45,55 50,55 59,55
INT: J7.2 J8.8 P8.2 | length 43.9
  Top Layer w0.2: J7.2@30.46,32.46 J7.2 31.256,31.864 J8.8 36.134,31.6 54.3,31.6 55.1,30.8 57.3,30.8 58,30.1 58,27.4 59.6,25.8 61.1,25.8 61.8,26.5 61.8,27.4 62.5,28.1 64.2,28.1 64.5,27.8 64.5,25.34 P8.2
IO13: J2.4 P12.1 | length 10
  Bottom Layer w0.2: J2.4 57.9,33.574 57.9,37.18 ; 58.3,37.58 57.9,37.18 ; P12.1 57.9,37.18
IO14: J2.10 P12.4 | length 17
  Bottom Layer w0.2: J2.10 58.4,18.834 58.4,30.06 P12.4
IO21: J8.16 P12.9 | length 27.6
  Top Layer w0.2: J8.16 36.544,11.544 42.7,17.7 58.74,17.7 P12.9
IO32: J2.9 P12.3 | length 17
  Bottom Layer w0.2: J2.9 57.9,20.874 57.9,30.4 59.2,31.7 59.2,33.4 P12.3
IO33: J2.7 P12.2 | length 14.5
  Bottom Layer w0.2: J2.7 57.4,25.454 57.4,30.6 58.7,31.9 58.7,35.44 P12.2
MISO: J6.5 J8.13 P1.5 | length 80.1
  Top Layer w0.2: J6.5 6.94,24.84 6.35,24.25 6.35,21.85 7.365,20.835 34.198,20.835 J8.13 ; v1(40.2,34.4) 48.8,34.4 55.1,40.7 61.4,40.7 61.9,40.2 61.9,38.64 P1.5
  Bottom Layer w0.2: J8.13 40.2,23.494 v1(40.2,34.4)
MOSI: J6.6 J8.12 P1.6 | length 71.3
  Top Layer w0.2: J6.6@7.6,22.3 J6.6@7.7,22.2 ; J6.6 28.6,22.3 29.7,21.2 35.366,21.2 J8.12 ; v1(39.6,33.5) 48.9,33.5 53.6,38.2 61,38.2 61.9,37.3 61.9,36.1 P1.6
  Bottom Layer w0.2: J8.12 37.504,21.704 39.6,23.8 v1(39.6,33.5)
NetJ2_11: J2.11 JP10.1 | length 3.6
  Bottom Layer w0.2: JP10.1 52.9,14.3 53.116,14.084 J2.11
NetJ2_12: J2.12 JP11.1 | length 3.7
  Bottom Layer w0.2: JP11.1 55.146,10.5 J2.12
NetJ4_1: J4.1 JP12.1 P4.1 | length 6.6
  Top Layer w0.2: J4.1 P4.1
  Bottom Layer w0.2: JP12.1 52.3,3.5 J4.1
NetJ4_6: J4.6 R9.2 | length 3.2
  Bottom Layer w0.2: J4.6 39.7,4.2 40.8,5.3 R9.2
NetJ7_5: J7.5 JP8.1 | length 4.4
  Bottom Layer w0.2: JP8.1 27.3,26.22 27.3,25.8 28.26,24.84 J7.5
NetJ7_6: J7.6 JP9.1 | length 3.4
  Bottom Layer w0.2: JP9.1 27.758,22.4 30.56,22.4 J7.6
NetJP13_2: JP13.2 R1.1 | length 2.1
  Bottom Layer w0.25: R1.1 26.1,50.4 26.531,49.969 26.6,49.9 JP13.2
NetJP14_2: JP14.2 R2.1 | length 1.6
  Bottom Layer w0.25: JP14.2 24.7,50.08 R2.1
NetLED1_1: LED1.1 R5.1 | length 1.4
  Top Layer w0.254: LED1.1 R5.1
PWM: J2.6 J7.1 P8.1 | length 44.5
  Top Layer w0.2: J7.1@30.46,35 29.2,33.74 29.2,31.9 29.9,31.2 34.1,31.2 34.5,30.8 54,30.8 54.4,30.4 56.8,30.4 57.4,29.8 57.4,26.8 ; J2.6 56.206,26.8 57.4,26.8 ; P8.1 62.02,25.4 58.3,25.4 57.4,26.3 57.4,26.8
RST: J2.8 J6.2 P1.2 R8.1 R9.1 | length 109.8
  Top Layer w0.2: J6.2 6.86,32.46 6.2,31.8 6.2,29.4 7,28.6 8.3,28.6
  Top Layer w0.203: 8.3,28.6 8.7,28.6 11.1,26.2 32.5,26.2 v1(33.2,25.5) 52.104,25.5 55.9,21.704 J2.8
  Bottom Layer w0.2: v1(33.2,25.5) 33.2,14.8 35.2,12.8 38,12.8 40.8,10 R9.1 R8.1 ; J2.8 55,22.894 55,32.5 55.5,33 56.5,33 57.4,33.9 57.4,38.9 ; 57.8,39.3 57.4,38.9 ; P1.2 63.16,44.66 57.4,38.9
RX: J4.4 J7.3 J8.14 P8.3 | length 63.1
  Top Layer w0.2: J8.14 36.524,16.624 40.3,20.4 57.5,20.4 57.8,20.7 62.4,20.7 P8.3
  Bottom Layer w0.2: J8.14 36.1,16.624 43.6,9.124 43.6,4.58 J4.4
  Bottom Layer w0.203: J7.3@30.46,29.92 31.68,29.92 34.4,27.2 34.4,18.094 J8.14
SCK: J6.4 J8.11 P1.4 | length 70.3
  Top Layer w0.2: J6.4@7.6,27.38 11.38,23.6 35.226,23.6 J8.11 ; v1@38.8,35.1 v1(39,35.1) 48.5,35.1 54.7,41.3 61.78,41.3 P1.4
  Bottom Layer w0.2: J8.11 39,27.374 39,34.9 v1@38.8,35.1
SCL: JP8.2 JP10.2 JP13.1 P2.4 P8.5 U1.2 | length 108.5
  Top Layer w0.2: P2.4 19.85,47.5 v1(26.9,47.5) 30.3,47.5 34.6,43.2 37.7,43.2 39.35,41.55 U1.2 ; v1(32.6,15) 32.6,12.9 35.1,10.4 37.8,10.4 42.8,15.4 v1(54.3,15.4) 62.18,15.4 P8.5
  Bottom Layer w0.2: 27.3,41.8 27.3,29.4 JP8.2 28.8,27.4 30.1,26.1 31.5,26.1 32.6,25 v1(32.6,15) ; JP10.2 53,15.4 v1(54.3,15.4)
  Bottom Layer w0.25: JP13.1 v1(26.9,47.5) 25.7,46.3 25.7,43.4 27.3,41.8
SDA: JP9.2 JP11.2 JP14.1 P2.3 P8.6 U1.1 | length 108.4
  Top Layer w0.2: P2.3 21.25,48.1 v1(24.7,48.1) 30.6,48.1 33,45.7 36.5,45.7 40.15,42.05 U1.1 ; v1(31.8,15) 31.8,12.5 34.6,9.7 39.4,9.7 42.6,12.9 v1(52.9,12.9) 60.7,12.9 61.98,14.18 P8.6
  Bottom Layer w0.2: v1(24.7,48.1) 24.7,43.1 26.6,41.2 26.6,29.4 25.3,28.1 25.3,22.3 26.2,21.4 JP9.2 28.8,21.4 29.1,21.1 30.841,21.1 31.8,20.141 v1(31.8,15) ; JP11.2 v1(52.9,12.9)
  Bottom Layer w0.25: v1(24.7,48.1) JP14.1
TX: J4.5 J7.4 J8.15 P8.4 | length 62.7
  Top Layer w0.2: J8.15 37.884,14.084 41.914,18.114 57.114,18.114 59.3,20.3 62.46,20.3 P8.4
  Bottom Layer w0.2: J7.4@30.46,27.38 32.72,27.38 33.9,26.2 33.9,16.054 J8.15 J8.15@35.87,14.03 ; J8.15@35.8,14.1 J8.15@35.87,14.03 ; J4.5 43.1,4.26 43.1,8.7 37.85,13.95 35.95,13.95 J8.15@35.87,14.03
pads on no net: J1.M J2.1 J2.2 J8.3 M1. M2.@35.87,11.544 M2.@56.19,11.544 U1.3 U3.5
copper on no net:
  other v1: 48.2,6.5

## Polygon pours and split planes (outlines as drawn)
GND on Top Layer "TOP_GND" (solid, remove dead copper, pour order 16): 0,56 0,0 65,0 65,56
GND on Bottom Layer "Bottom Layer-No Net" (solid, remove dead copper, pour order 14): 0,56 0,0 65,0 65,56

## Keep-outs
Keep-Out Layer:
  circle w0.2: c30.025,40.08 r2
  circle w0.2: c8.435,40.08 r2
  circle w0.2: c8.435,54.43 r2
  circle w0.2: c30.025,54.43 r2
  circle w0.2: c19.23,32.46 r2
  lines w0.2: 0,3 ccw(c3,3) 3,0 62,0 ccw(c62,3) 65,3 65,53 ccw(c62,53) 62,56 3,56 ccw(c3,53) 0,53 0,3

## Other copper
Bottom Layer:
  rectangle net GND: 24.3,5.9 29.2,7.6
  rectangle net GND: 25,5.2 25.9,11.7
  rectangle net GND: 27.3,5.4 28.4,8.4
  rectangle net +5V: 46.5,9.6 47.7,10
  rectangle net +3V3_ESP: 49.5,8.5 50,9.3
  pour cut-out: 46.6,41.4 ccw(c47.6,41.4) 47.6,40.4 ccw(c47.6,41.4) 48.6,41.4 ccw(c47.6,41.4) 47.6,42.4 ccw(c47.6,41.4)
  pour cut-out: 49.1,41.4 ccw(c50.1,41.4) 50.1,40.4 ccw(c50.1,41.4) 51.1,41.4 ccw(c50.1,41.4) 50.1,42.4 ccw(c50.1,41.4)
  pour cut-out: 51.6,41.4 ccw(c52.6,41.4) 52.6,40.4 ccw(c52.6,41.4) 53.6,41.4 ccw(c52.6,41.4) 52.6,42.4 ccw(c52.6,41.4)

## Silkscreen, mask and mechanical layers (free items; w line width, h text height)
Top Overlay:
  lines w0.254: 38,0.5 54.1,0.5 54.1,2.1 38,2.1 38,0.5
  text "3V3" at 20.8,47.5 h1.2 r90
  text "SCL" at 16.7,47.1 h1.2 r90
  text "SDA" at 18.8,47.1 h1.2 r90
  text "GND" at 22.8,47.1 h1.2 r90
  text "MBL" at 61.8,45 h1.8 r90
  text "+5V_1  GND" at 7.5,42.7 h1.2
  text "+5V_2  GND" at 25.1,42.7 h1.2
  text "FRESET" at 33,42.3 h1.2 r90
  text "BOKRA / Adafruit Feather / Adapter" at 11.7,38.8 h2
  text "MBR" at 61.8,8.2 h1.8 r90
  text "EN" at 55.5,0.6 h1.8
Bottom Overlay:
  drawing of 502 lines, arcs and shapes, not listed
  text "SDA" at 23.7,46.3 h0.8 r270
  text "SCL" at 25.9,46.3 h0.8 r270
  text "+3V3J2" at 44.2,44.7 h0.8
  text "ADDR1" at 49.8,36.6 h0.8 r270
  text "ADDR0" at 47.2,36.3 h0.8 r270
  text "ADDR2" at 52.2,36.3 h0.8 r270
  text "+5VJ2" at 52.7,31.9 h0.8
  text "mikro" at 22.367,27.801 h2.79
  text "BUS" at 22.367,24.995 h3.43
  text "SCL_J1" at 27.6,24.75 h0.8
  text "+5VJ1" at 5.8,22.9 h0.8
  text "SDA_J1" at 27.6,19.95 h0.8
  text "+3V3J1" at 6.1,17.9 h0.8
  text "SCL_J2" at 53.3,13 h0.8
  text "SDA_J2" at 58.4,9.5 h0.8
  text "ESP_EN" at 55.7,4.6 h0.8
  text "Rev 1.21" at 12.8,2.2 h1.4
Mechanical 15:
  the board outline again, w0.2
Drill Drawing:
  drawing of 210 lines, arcs and shapes, not listed
  text "PCB requirements" at 125.554,97.385 h1
  text "List of Gerber files" at 168.954,97.385 h1
  text "Parameter" at 123.054,94.385 h1
  text "Value" at 142.154,94.385 h1
  text "File" at 162.254,94.385 h1
  text "No." at 156.054,93.385 h1
  text "Description" at 174.554,93.385 h1
  text "Generated" at 190.954,93.385 h1
  text "extension" at 160.354,92.285 h1
  text "Material" at 112.154,91.385 h1
  text "FR-4" at 139.154,91.385 h1
  text "Number of layers" at 112.154,88.385 h1
  text "2" at 139.154,88.385 h1
  text "1." at 156.254,88.385 h1
  text "GTL" at 163.254,88.385 h1
  text "Top Overlay (Silk)" at 170.254,88.385 h1
  text "Board thickness" at 112.154,85.385 h1
  text "1.6 mm" at 139.154,85.385 h1
  text "2." at 156.254,85.385 h1
  text "GTS" at 163.254,85.385 h1
  text "Top Solder Mask" at 170.254,85.385 h1
  text "Cu thickness" at 112.154,82.385 h1
  text "1 oz (35 um)" at 139.154,82.385 h1
  text "3." at 156.454,82.385 h1
  text "GTO" at 163.254,82.385 h1
  text "Top Layer" at 170.254,82.385 h1
  text "Solder mask" at 112.154,79.385 h1
  text "Red" at 139.154,79.385 h1
  text "4." at 156.454,79.385 h1
  text "G1" at 163.254,79.385 h1
  text "Mid Layer 1" at 170.254,79.385 h1
  text "Surface finishing" at 112.154,76.385 h1
  text "HAL" at 139.154,76.385 h1
  text "5." at 156.454,76.385 h1
  text "G2" at 163.254,76.385 h1
  text "Mid Layer 2" at 170.254,76.385 h1
  text "Silkscreen" at 112.154,73.385 h1
  text "6." at 156.454,73.385 h1
  text "GBL" at 163.254,73.385 h1
  text "Bottom Layer" at 170.254,73.385 h1
  text "Top - white / Bottom - white" at 138.9,72.2 h0.8
  text "Min. line to line clearance" at 112.154,70.385 h1
  text "0.15 mm" at 139.154,70.385 h1
  text "7." at 156.454,70.385 h1
  text "GBS" at 163.254,70.385 h1
  text "Bottom Solder Mask" at 170.254,70.385 h1
  text "Min. line thickness" at 112.154,67.385 h1
  text "0.15 mm" at 139.154,67.385 h1
  text "8." at 156.454,67.385 h1
  text "GBO" at 163.254,67.385 h1
  text "Bottom Overlay (Silk)" at 170.254,67.385 h1
  text "Board dimension" at 112.154,64.385 h1
  text "65x56 mm" at 139.154,64.385 h1
  text "9." at 156.454,64.385 h1
  text "GM9" at 163.254,64.385 h1
  text "Bottom PSM" at 170.254,64.385 h1
  text "Panelization" at 112.154,61.385 h1
  text "No" at 139.154,61.385 h1
  text "10." at 156.454,61.385 h1
  text "GM15" at 163.254,61.385 h1
  text "Board Layer" at 170.254,61.385 h1
  text "RoHS compatibility" at 112.154,58.385 h1
  text "Yes" at 139.154,58.385 h1
  text "11." at 156.454,58.385 h1
  text "GM7" at 163.254,58.385 h1
  text "Milling" at 170.254,58.385 h1
  text "12." at 156.454,55.385 h1
  text "GM8" at 163.254,55.385 h1
  text "V-Cut" at 170.254,55.385 h1
  text "13." at 156.454,52.385 h1
  text "TXT" at 163.254,52.385 h1
  text "Round Holes" at 170.254,52.385 h1
  text "14." at 156.454,49.385 h1
  text "TXT" at 163.254,49.385 h1
  text "Slot Holes" at 170.254,49.385 h1
  text "Layer stack up details" at 144.754,43.735 h1
  text "Copper" at 143.154,40.735 h1
  text "Dielectric" at 152.954,40.735 h1
  text "Dielectric" at 165.954,40.735 h1
  text "Dielectric" at 178.254,40.735 h1
  text "Layer name" at 125.154,39.735 h1
  text "thickness" at 141.454,38.335 h1
  text "height" at 154.754,38.335 h1
  text "material" at 166.854,38.335 h1
  text "type" at 181.154,38.335 h1
  text "Top Layer (GTL)" at 122.154,31.735 h1
  text "0.035 mm" at 141.954,31.735 h1
  text "1.55 mm" at 154.654,22.735 h1
  text "FR-4" at 167.754,22.735 h1
  text "Core" at 179.754,22.735 h1
  text "Bottom Layer (GBL)" at 122.154,13.735 h1
  text "0.035 mm" at 141.954,13.735 h1
  text "Symbol" at 112.639,4.971 h1.01
  text "Count" at 119.79,4.971 h1.01
  text "Hole Size" at 128.253,4.971 h1.01
  text "Plated" at 144.455,4.971 h1.01
  text "Hole Type" at 151.606,4.971 h1.01
  text "Hole Length" at 161.965,4.971 h1.01
  text "149" at 119.79,2.86 h0.84
  text "0.300mm (11.81mil)" at 128.253,2.86 h0.84
  text "PTH" at 144.455,2.86 h0.84
  text "Round" at 151.606,2.86 h0.84
  text "-" at 161.965,2.86 h0.84
  text "3" at 119.79,0.748 h0.84
  text "0.500mm (19.69mil)" at 128.253,0.748 h0.84
  text "PTH" at 144.455,0.748 h0.84
  text "Slot" at 151.606,0.748 h0.84
  text "1.700mm (66.93mil)" at 161.965,0.748 h0.84
  text "C" at 112.224,0.598 h0.94
  text "10" at 119.79,-1.363 h0.84
  text "0.800mm (31.50mil)" at 128.253,-1.363 h0.84
  text "PTH" at 144.455,-1.363 h0.84
  text "Round" at 151.606,-1.363 h0.84
  text "-" at 161.965,-1.363 h0.84
  text "16" at 119.79,-3.475 h0.84
  text "0.889mm (35.00mil)" at 128.253,-3.475 h0.84
  text "PTH" at 144.455,-3.475 h0.84
  text "Round" at 151.606,-3.475 h0.84
  text "-" at 161.965,-3.475 h0.84
  text "38" at 119.79,-5.587 h0.84
  text "0.900mm (35.43mil)" at 128.253,-5.587 h0.84
  text "PTH" at 144.455,-5.587 h0.84
  text "Round" at 151.606,-5.587 h0.84
  text "-" at 161.965,-5.587 h0.84
  text "28" at 119.79,-7.698 h0.84
  text "1.000mm (39.37mil)" at 128.253,-7.698 h0.84
  text "PTH" at 144.455,-7.698 h0.84
  text "Round" at 151.606,-7.698 h0.84
  text "-" at 161.965,-7.698 h0.84
  text "1" at 119.79,-9.81 h0.84
  text "1.200mm (47.24mil)" at 128.253,-9.81 h0.84
  text "NPTH" at 144.455,-9.81 h0.84
  text "Round" at 151.606,-9.81 h0.84
  text "-" at 161.965,-9.81 h0.84
  text "5" at 119.79,-11.921 h0.84
  text "2.000mm (78.74mil)" at 128.253,-11.921 h0.84
  text "NPTH" at 144.455,-11.921 h0.84
  text "Round" at 151.606,-11.921 h0.84
  text "-" at 161.965,-11.921 h0.84
  text "4" at 119.79,-14.033 h0.84
  text "2.540mm (100.00mil)" at 128.253,-14.033 h0.84
  text "PTH" at 144.455,-14.033 h0.84
  text "Round" at 151.606,-14.033 h0.84
  text "-" at 161.965,-14.033 h0.84
  text "4" at 119.79,-16.144 h0.84
  text "2.750mm (108.27mil)" at 128.253,-16.144 h0.84
  text "PTH" at 144.455,-16.144 h0.84
  text "Round" at 151.606,-16.144 h0.84
  text "-" at 161.965,-16.144 h0.84
  text "258 Total" at 119.79,-18.256 h0.84
  text "Slot definitions :" at 112.639,-20.315 h0.84
  text "Routed Path Length" at 127.203,-20.315 h0.84
  text "= Calculated from tool start centre position to tool end centre position." at 142.751,-20.315 h0.84
  text "Hole Length" at 127.203,-21.741 h0.84
  text "= Routed Path Length + Tool Size = Slot length as defined in the PCB layout" at 136.981,-21.741 h0.84
  text "Additional requests" at 122.154,-38.615 h1
  text "None." at 121.804,-41.64 h1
